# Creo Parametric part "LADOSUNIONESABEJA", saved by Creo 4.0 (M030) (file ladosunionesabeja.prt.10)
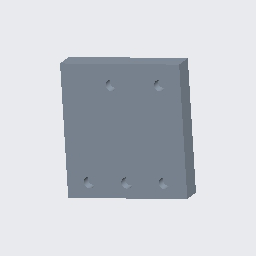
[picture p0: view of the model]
Units: millimeter Newton Second (mmNs); MM, TONNE, SECS

Created from: MMNS_PART_SOLID.PRT

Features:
  1. datum plane "RIGHT"
  2. datum plane "TOP"
  3. datum plane "FRONT"
  4. coordinate system
  5. sketch "Sketch 1"
  6. extrusion "Extrude 1"
  7. pattern "Pattern 1"
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
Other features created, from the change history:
  hole "Hole 1"
  hole "Hole 1 [2]"
  hole "Hole 1 [3]"
  hole "Hole 2"
  pattern "Patrón 2"
  hole "Taladro 2 [2]"
  hole "Hole 3"
  pattern "Pattern 3"
  hole "Hole 3 [2]"

Surfaces: 13 plane, 7 cylinder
